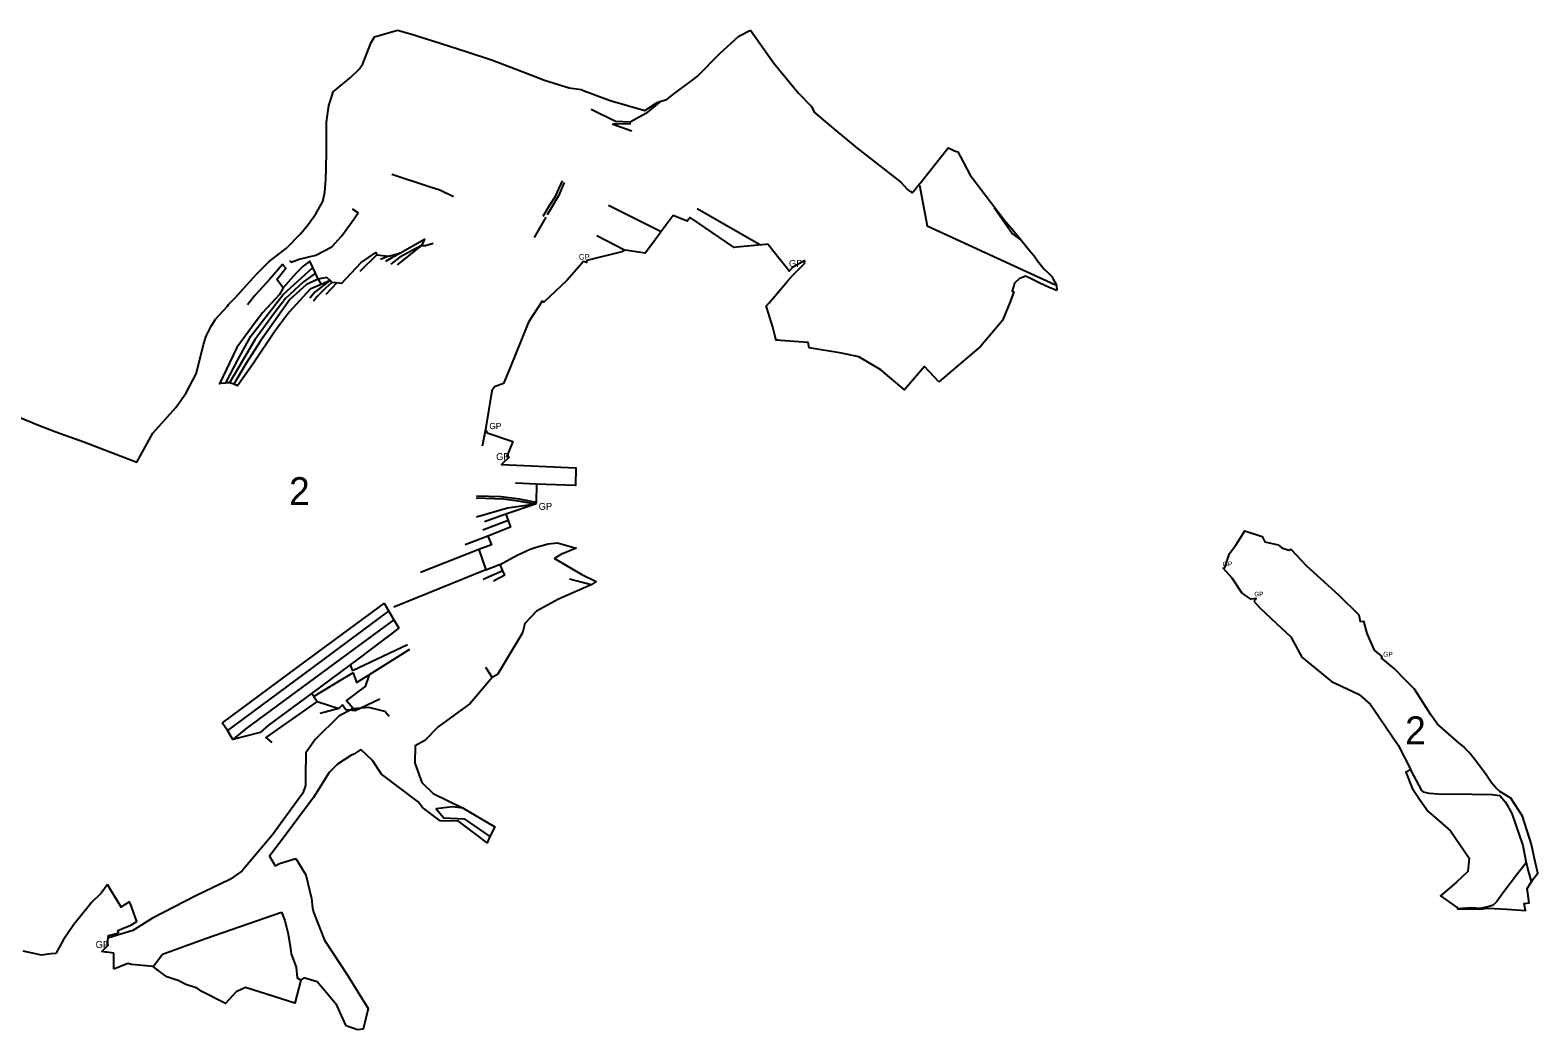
# Model space of a CAD drawing. Extents: x -584576 to -579722, y -1113169 to -1110375.
# Drawn here: x -581887 to -579722, y -1111900 to -1110466 of the extents above; entities that cross this region are included whole.
import ezdxf

# ---------------------------------------------------------------- set-up
doc = ezdxf.new("R2010")
doc.units = 0
for name, color, linetype in [('CESTY', 7, 'Continuous'), ('GRA_ZV', 7, 'Continuous'), ('LES_ZV', 7, 'Continuous'), ('Level 255', 7, 'Continuous'), ('OVNE_PRE', 7, 'Continuous'), ('OVNE_SET', 7, 'Continuous'), ('OVNI_PRE', 7, 'Continuous'), ('OVNI_SET', 7, 'Continuous'), ('VODA', 7, 'Continuous')]:
    doc.layers.add(name, color=color, linetype=linetype)

msp = doc.modelspace()

# ---------------------------------------------------------------- linework, layer by layer
at = {"layer": 'CESTY'}
msp.add_lwpolyline([(-580609.5, -1110688), (-580598.4, -1110746.4), (-580414.4, -1110831.3)], dxfattribs=at)
at = {"layer": 'GRA_ZV'}
for points in [[(-581671.3, -1111831), (-581672.7, -1111830.2), (-581680.3, -1111827.8), (-581690.3, -1111824.6), (-581699.5, -1111817.6), (-581709.9, -1111809.7), (-581696.5, -1111791.9), (-581633.3, -1111769.1), (-581525.9, -1111731.6)], [(-581525.9, -1111731.6), (-581520.9, -1111743.4), (-581516.1, -1111763), (-581512.9, -1111783.8), (-581511.6, -1111791.6), (-581504.7, -1111810.5), (-581503.4, -1111825.7), (-581497.7, -1111829.2), (-581506.3, -1111862.2), (-581577.4, -1111839.9), (-581590.8, -1111845.9), (-581606.2, -1111862.6), (-581640.1, -1111845.6), (-581646.8, -1111840.6), (-581663.1, -1111835.4), (-581666, -1111833.9), (-581671.3, -1111831)]]:
    msp.add_lwpolyline(points, dxfattribs=at)
at = {"layer": 'LES_ZV'}
for p, q in [((-580981.2, -1110567.8), (-581002.5, -1110585.3)), ((-581146.1, -1110734.1), (-581163.1, -1110763.4)), ((-581055.9, -1110716.7), (-580980.7, -1110754.9)), ((-580928.8, -1110721.5), (-580837.9, -1110773.8)), ((-581388.6, -1110788.3), (-581413.1, -1110812.3)), ((-581371.9, -1110790.2), (-581383.6, -1110794.9)), ((-581355.6, -1110785.9), (-581376.1, -1110797.6)), ((-581477.3, -1110841.4), (-581485.1, -1110850.5)), ((-581456.9, -1110825.7), (-581468.8, -1110830.8)), ((-581446.3, -1110828.4), (-581461.8, -1110845)), ((-581474.6, -1110848.2), (-581479.8, -1110854.6)), ((-581232.9, -1111038.7), (-581237.3, -1111062.8)), ((-581159.3, -1111117.2), (-581189.5, -1111115.7)), ((-581161.1, -1111146.2), (-581201.3, -1111151.6)), ((-581201.3, -1111151.6), (-581245.9, -1111164.6)), ((-581203.5, -1111160.5), (-581234.3, -1111171.2)), ((-581200.3, -1111169.5), (-581236.7, -1111183.5)), ((-581242.4, -1111211.2), (-581325.9, -1111244.2)), ((-581229.4, -1111191.9), (-581262.1, -1111204.3)), ((-581232.4, -1111240.4), (-581364.6, -1111293.9)), ((-581208, -1111241.6), (-581236.1, -1111254.2)), ((-581205.1, -1111248.1), (-581221.2, -1111256.7)), ((-581081.1, -1111261.8), (-581112.1, -1111253.9)), ((-581344.9, -1111347.9), (-581423.7, -1111385.2)), ((-581341.8, -1111354.5), (-581400, -1111390.9)), ((-581426.9, -1111376.5), (-581423.7, -1111385.2)), ((-581232.8, -1111380.1), (-581223.1, -1111394.7)), ((-581419.7, -1111442.1), (-581384.7, -1111425.4)), ((-581443.5, -1111439.1), (-581470.3, -1111446.4))]:
    msp.add_line(p, q, dxfattribs=at)
for points in [[(-581002.5, -1110585.3), (-581024.8, -1110597.6), (-581046.3, -1110596.6), (-581080.8, -1110579.4)], [(-581023.9, -1110600.3), (-581050.1, -1110600.6), (-581022.4, -1110610.4)], [(-581278.5, -1110704.7), (-581298.4, -1110695.5), (-581313.4, -1110690.6), (-581367.1, -1110672.7)], [(-581122.8, -1110681.8), (-581127.8, -1110693.2), (-581133.1, -1110705.6), (-581141.3, -1110717.7), (-581150.4, -1110733)], [(-581119.9, -1110684.3), (-581127.9, -1110703.3), (-581144.4, -1110730.9)], [(-581514.3, -1110796.2), (-581511.8, -1110798.6), (-581500.1, -1110794.6), (-581476.2, -1110788.5), (-581453.5, -1110776.9), (-581439.3, -1110761.6), (-581425.1, -1110741.9), (-581415.4, -1110727.8), (-581423.7, -1110722.4)], [(-581439.3, -1110829.1), (-581411.1, -1110799.2), (-581390.4, -1110784.8), (-581388.6, -1110788.3), (-581371.9, -1110790.2), (-581355.6, -1110785.9), (-581320.1, -1110765.6), (-581324.5, -1110774.6), (-581318.8, -1110774.8), (-581307.7, -1110771.6)], [(-581324.5, -1110774.6), (-581355.7, -1110791.6), (-581368.7, -1110801.5)], [(-581324.5, -1110774.6), (-581354.9, -1110798.5), (-581359.6, -1110802.5)], [(-581032, -1110781.3), (-581034.1, -1110781), (-581072.9, -1110760.8)], [(-581439.3, -1110829.1), (-581446.3, -1110828.4), (-581453.2, -1110827.8), (-581455.7, -1110825.2), (-581460.7, -1110820.6), (-581472.9, -1110822.9), (-581476.8, -1110814.7), (-581480.9, -1110806.2), (-581485.2, -1110797.1), (-581494.6, -1110804.4), (-581504.6, -1110814.6), (-581523.4, -1110835.5)], [(-581523.4, -1110835.5), (-581528.5, -1110844.9), (-581552.8, -1110871.6), (-581563.6, -1110885.2), (-581590, -1110921.2), (-581614.7, -1110973.2), (-581613.1, -1110972.3), (-581605.7, -1110972.1), (-581588.3, -1110939), (-581569.5, -1110905), (-581523.4, -1110845), (-581480.9, -1110806.2)], [(-581476.8, -1110814.7), (-581494.1, -1110827.1), (-581519.8, -1110850.6), (-581537, -1110873.1), (-581563.8, -1110910.3), (-581581.9, -1110940.2), (-581600.2, -1110971.9), (-581605.7, -1110972.1)], [(-581472.9, -1110822.9), (-581489.6, -1110830.9), (-581513.5, -1110852.1), (-581556.3, -1110912.7), (-581577, -1110944.4), (-581594.2, -1110973.9), (-581600.2, -1110971.9)], [(-581472.9, -1110822.9), (-581468.8, -1110830.8), (-581484.4, -1110837.5), (-581514.9, -1110870.5), (-581534.8, -1110897.2), (-581566.6, -1110945.3), (-581588.7, -1110976.3), (-581594.2, -1110973.9)], [(-581521.7, -1110804.7), (-581524.4, -1110801.9), (-581543, -1110823.8), (-581563.6, -1110846.1), (-581574.4, -1110860.1)], [(-581523.4, -1110835.5), (-581532.2, -1110823.6), (-581519.3, -1110807.1), (-581521.7, -1110804.7)], [(-581455.7, -1110825.2), (-581456.9, -1110825.7), (-581477.3, -1110841.4)], [(-581453.2, -1110827.8), (-581462.8, -1110836.4), (-581474.6, -1110848.2)], [(-581161.1, -1111146.2), (-581185.7, -1111141.5), (-581206.8, -1111139), (-581246, -1111137.2)], [(-581160, -1111143), (-581162.2, -1111143), (-581184, -1111139), (-581210.5, -1111135.7), (-581245.7, -1111134.6)], [(-581205.1, -1111248.1), (-581208, -1111241.6), (-581211.8, -1111232.4)], [(-581378.1, -1111287.9), (-581490.9, -1111370.9), (-581610.8, -1111460)], [(-581371.6, -1111299.3), (-581468.6, -1111371.2), (-581603.3, -1111471)], [(-581378.1, -1111287.9), (-581364.4, -1111311.9), (-581357.1, -1111324.2)], [(-581364.4, -1111311.9), (-581423.7, -1111355.5), (-581576.6, -1111467.9), (-581595.4, -1111483.8)], [(-581357.1, -1111324.2), (-581415.9, -1111368.3), (-581426.9, -1111376.5), (-581482.5, -1111417.7), (-581544.4, -1111463.1), (-581556.1, -1111473.7)], [(-581422.9, -1111387.9), (-581439, -1111397.8), (-581479.3, -1111421.9), (-581482.5, -1111417.7)], [(-581400, -1111390.9), (-581405.5, -1111407.5), (-581414.2, -1111414), (-581432.2, -1111427.9), (-581419.7, -1111442.1)], [(-581422.9, -1111387.9), (-581417.9, -1111402.2), (-581400, -1111390.9)], [(-581474.6, -1111429.1), (-581548, -1111480.7), (-581539.5, -1111487.9)], [(-581479.3, -1111421.9), (-581474.6, -1111429.1), (-581443.5, -1111439.1), (-581438, -1111434), (-581433.4, -1111440.6), (-581419.7, -1111442.1)], [(-581556.1, -1111473.7), (-581595.4, -1111483.8), (-581603.3, -1111471), (-581610.8, -1111460)], [(-581265, -1111582.5), (-581280.2, -1111580.2), (-581303.5, -1111583.3), (-581292.7, -1111596.4), (-581263.5, -1111597.7), (-581226.4, -1111623)]]:
    msp.add_lwpolyline(points, dxfattribs=at)
at = {"layer": 'Level 255'}
for p, q in [((-581127.9, -1110703.3), (-581127.9, -1110703.3)), ((-581224.3, -1111204.3), (-581224.3, -1111204.3)), ((-581414.5, -1111406.5), (-581414.5, -1111406.5))]:
    msp.add_line(p, q, dxfattribs=at)
at = {"layer": 'OVNE_PRE'}
for p, q in [((-581308.6, -1110481), (-581260.6, -1110496.5)), ((-580928.7, -1110532.1), (-580896.3, -1110499.3)), ((-580076.3, -1111336.6), (-580060.6, -1111365.6)), ((-579978.2, -1111419), (-579962.2, -1111433.2)), ((-581746.4, -1111805.5), (-581746.4, -1111805.5))]:
    msp.add_line(p, q, dxfattribs=at)
for points in [[(-581926, -1111011.8), (-581883.7, -1111028.7), (-581879.2, -1111030.5), (-581849.5, -1111042.4), (-581809.7, -1111056.4), (-581733.6, -1111085.8), (-581710.2, -1111044.1), (-581677.3, -1111007.2), (-581672.4, -1111000.4), (-581662.4, -1110986.4), (-581648.1, -1110959), (-581647.3, -1110955.7), (-581637.7, -1110916.8), (-581634.3, -1110906.4), (-581633.4, -1110903.7), (-581626.5, -1110890.7), (-581621.7, -1110882.7), (-581620.3, -1110880.4), (-581603.3, -1110861.6), (-581601.6, -1110859.6), (-581593.4, -1110851.4), (-581591.5, -1110849.4), (-581575.6, -1110831.4), (-581561.3, -1110815.3), (-581543.5, -1110797.5), (-581518.6, -1110778.4), (-581498.2, -1110758.2), (-581487.6, -1110744.5), (-581476.6, -1110729.4), (-581466.5, -1110711.4), (-581463.6, -1110698.3), (-581462, -1110680.1), (-581461.3, -1110664.1), (-581461, -1110639.9), (-581461, -1110597.8), (-581457.5, -1110573.8), (-581455, -1110565.2), (-581451.7, -1110554.2), (-581427.3, -1110533.9), (-581414.1, -1110521.7), (-581408.7, -1110513.8), (-581397.2, -1110484.4), (-581392, -1110475.4), (-581358.9, -1110465.7)], [(-580896.3, -1110499.3), (-580868.9, -1110474.5), (-580852.1, -1110465.9)], [(-581260.6, -1110496.5), (-581222.9, -1110508.6), (-581173.7, -1110527.6), (-581148, -1110537.5), (-581112.5, -1110548.7), (-581095.3, -1110551), (-581091.1, -1110552.6), (-581078, -1110557.7), (-581053.8, -1110566.5), (-581003.8, -1110580.8), (-580998.6, -1110577.5), (-580986.2, -1110569.4), (-580981.2, -1110567.8), (-580972.4, -1110565.1), (-580964.5, -1110558.9), (-580958.8, -1110554.7), (-580955.1, -1110551.9)]]:
    msp.add_lwpolyline(points, dxfattribs=at)
at = {"layer": 'OVNE_SET'}
for p, q in [((-580980.7, -1110754.9), (-580980.7, -1110754.9)), ((-580521.9, -1110919.5), (-580569.3, -1110959.8)), ((-581212.5, -1111232.7), (-581211.8, -1111232.4)), ((-580125.6, -1111281.4), (-580129.7, -1111285.3)), ((-581334.2, -1111517.8), (-581324, -1111545.7)), ((-581505.1, -1111654.5), (-581490.5, -1111677.8)), ((-581482.1, -1111714.2), (-581482.1, -1111714.2)), ((-581481.2, -1111725.5), (-581481.2, -1111725.5)), ((-581481.2, -1111725.5), (-581479.7, -1111731.5)), ((-581746.4, -1111805.5), (-581766.5, -1111813.6))]:
    msp.add_line(p, q, dxfattribs=at)
for points in [[(-581358.9, -1110465.7), (-581337.3, -1110472.1), (-581328.7, -1110474.6), (-581317.6, -1110478.1), (-581308.6, -1110481)], [(-580852.1, -1110465.9), (-580818.7, -1110513.2), (-580783.3, -1110555.9), (-580765, -1110575), (-580760.4, -1110583.8), (-580732.7, -1110607.4), (-580699.2, -1110634.9), (-580636.2, -1110683.9), (-580627.3, -1110693.7), (-580624, -1110697), (-580621.7, -1110697.5)], [(-580955.1, -1110551.9), (-580937, -1110538.4), (-580928.7, -1110532.1)], [(-580621.7, -1110697.5), (-580620.2, -1110699.3), (-580618.4, -1110697.2), (-580612.3, -1110689.8), (-580608.9, -1110685.8), (-580608.1, -1110684.8), (-580604.7, -1110680.4), (-580568.3, -1110634.8), (-580564.2, -1110636.5), (-580559.2, -1110638.7), (-580554.4, -1110640.5), (-580551, -1110646.7), (-580536.6, -1110673.9), (-580533.4, -1110678.1), (-580487.8, -1110737.9), (-580468.6, -1110760.5), (-580451.6, -1110782.1), (-580444.8, -1110789.6), (-580440, -1110796.7), (-580430.7, -1110808.6), (-580424.9, -1110813.9), (-580419.5, -1110819.3), (-580417.5, -1110823.3), (-580413, -1110831.9), (-580412.4, -1110839.4)], [(-580827.4, -1110772.9), (-580830.9, -1110773.2), (-580872.3, -1110777), (-580875.8, -1110777.4), (-580938.8, -1110734.4), (-580943.1, -1110739.8), (-580963.5, -1110731.5), (-580980.7, -1110754.9), (-580982.6, -1110757.6), (-580995.8, -1110775.8), (-581003.3, -1110785.7), (-581032, -1110781.3), (-581036.9, -1110783.8), (-581087.3, -1110796.1), (-581087.7, -1110799.4), (-581092, -1110797.6), (-581116, -1110825.2), (-581149.1, -1110856), (-581151.6, -1110854.8), (-581171.1, -1110884.9), (-581197.4, -1110949.7), (-581206.7, -1110972.7)], [(-580774.1, -1110796.5), (-580791.9, -1110806.4), (-580796.5, -1110811.7), (-580801.2, -1110806), (-580803.6, -1110803.1), (-580813.5, -1110790.4), (-580827.4, -1110772.9)], [(-580582, -1110970.3), (-580602.3, -1110948.6), (-580630.9, -1110981.7), (-580665.3, -1110953.2), (-580696.7, -1110934.7), (-580721.5, -1110929.2), (-580768.2, -1110921.5), (-580769.2, -1110913.9), (-580809, -1110911), (-580812.7, -1110910.7), (-580815.4, -1110910.5), (-580817.2, -1110903.4), (-580820.1, -1110892.1), (-580828.8, -1110864), (-580829.5, -1110861.7), (-580825.9, -1110857.5), (-580817.2, -1110847.5), (-580799.2, -1110826.1), (-580792.1, -1110817.8), (-580774.8, -1110800.6), (-580774.1, -1110796.5)], [(-580412.4, -1110839.4), (-580416.1, -1110838.1), (-580421, -1110836.1), (-580423.3, -1110835.1), (-580435.7, -1110829.2), (-580451.2, -1110821.5), (-580457.5, -1110818.8), (-580466.5, -1110822.5), (-580473.2, -1110828.7)], [(-580473.2, -1110828.7), (-580476.6, -1110840.3), (-580474.1, -1110841.5), (-580479.4, -1110855.7), (-580490.5, -1110882.4), (-580521.9, -1110919.5)], [(-581206.7, -1110972.7), (-581219.8, -1110977.8), (-581223.8, -1110983.4), (-581232.9, -1111038.7)], [(-580569.3, -1110959.8), (-580570.3, -1110960.7), (-580573.4, -1110963.3), (-580582, -1110970.3)], [(-581232.9, -1111038.7), (-581230.4, -1111043.6), (-581193.4, -1111055.9), (-581202.1, -1111077.1), (-581198.7, -1111078.7), (-581209.8, -1111089.1), (-581103, -1111093.7), (-581103.6, -1111119.1), (-581159.3, -1111117.2), (-581160, -1111143), (-581161.1, -1111146.2), (-581203.5, -1111160.5), (-581200.3, -1111169.5)], [(-581200.3, -1111169.5), (-581196.9, -1111179.1), (-581229.4, -1111191.9)], [(-580125.6, -1111281.4), (-580133.9, -1111282.6), (-580146.5, -1111273.2), (-580160.7, -1111252), (-580173.5, -1111237.8), (-580171.3, -1111236.8), (-580164.4, -1111216.8), (-580155.1, -1111205), (-580142.3, -1111184.4), (-580117.5, -1111192.4), (-580113.7, -1111199.9), (-580094.4, -1111204.5), (-580089.1, -1111208.9), (-580079.3, -1111212.2), (-580076.5, -1111210.8), (-580053.8, -1111234.5), (-580008, -1111276.3), (-579978.5, -1111304.8), (-579976.7, -1111314.4), (-579971.8, -1111314), (-579967.2, -1111331.5), (-579956.7, -1111355.7), (-579945.7, -1111364.6), (-579946.4, -1111366.8)], [(-581211.8, -1111232.4), (-581187.4, -1111219.2), (-581168.5, -1111210.4), (-581159.8, -1111207.5), (-581142.6, -1111203.1), (-581129.2, -1111201.6), (-581102.5, -1111209.1), (-581124.7, -1111218.2), (-581133.7, -1111224.1), (-581094.6, -1111246.9), (-581073.9, -1111256.9), (-581081.1, -1111261.8), (-581128, -1111282.4), (-581159.3, -1111299.8), (-581176.2, -1111317.1), (-581179.8, -1111330.6), (-581215.4, -1111390.3), (-581223.1, -1111394.7), (-581254.9, -1111432), (-581300.5, -1111465.7), (-581320, -1111485), (-581333.5, -1111492.7), (-581334.2, -1111517.8)], [(-581229.4, -1111191.9), (-581224.3, -1111204.3), (-581242.4, -1111211.2), (-581232.4, -1111240.4), (-581212.5, -1111232.7)], [(-580129.7, -1111285.3), (-580120.2, -1111295.4), (-580089.9, -1111323.9), (-580076.3, -1111336.6)], [(-580060.6, -1111365.6), (-580047, -1111376.7), (-580018.1, -1111400.3), (-579988.4, -1111414.2), (-579978.2, -1111419)], [(-579962.2, -1111433.2), (-579957.8, -1111439.8), (-579922.4, -1111491.9), (-579921.6, -1111493), (-579904.7, -1111526.5), (-579910.5, -1111530.4), (-579911, -1111530.7), (-579902, -1111553.4), (-579890.4, -1111570.7), (-579879, -1111587.1), (-579862.3, -1111601.4), (-579846.9, -1111615.1), (-579820.1, -1111654.2), (-579822, -1111673.2), (-579839, -1111689.2), (-579861.6, -1111708.1), (-579837.1, -1111725.5), (-579836.9, -1111727), (-579801.2, -1111726.6), (-579797.1, -1111726.3), (-579793.6, -1111726), (-579766, -1111727.5), (-579739.6, -1111729.3), (-579740, -1111727), (-579741.3, -1111719.2), (-579734.3, -1111718.1), (-579737, -1111697.8), (-579732.7, -1111690.8), (-579728.9, -1111684.9), (-579721.7, -1111675.7), (-579727, -1111652.9), (-579730.7, -1111634.6), (-579743.8, -1111593.9), (-579760.6, -1111568.2), (-579776.3, -1111558.5), (-579781.4, -1111553.6), (-579788.2, -1111546.2), (-579796, -1111534.5), (-579802, -1111525.8), (-579812.5, -1111512), (-579818.6, -1111504.9), (-579820.8, -1111501.8), (-579826.5, -1111496.4), (-579828, -1111494.2), (-579834.4, -1111488.9), (-579865.8, -1111461.6), (-579875.1, -1111448.2), (-579898.8, -1111411.7), (-579910.8, -1111399.5), (-579927.8, -1111381.9), (-579944.9, -1111368), (-579946.4, -1111366.8)], [(-581411.6, -1111498.2), (-581421.9, -1111504.8), (-581426.1, -1111506.9), (-581445.4, -1111519.3), (-581457.1, -1111531.1), (-581479.7, -1111566.8), (-581523.3, -1111625.5)], [(-581324, -1111545.7), (-581307.8, -1111561.3), (-581265, -1111582.5), (-581219.3, -1111609), (-581226.4, -1111623), (-581230.2, -1111632.1), (-581271.6, -1111600.9), (-581297.8, -1111600.7), (-581323.2, -1111581.6), (-581329.6, -1111573.3), (-581382, -1111533.3), (-581395.1, -1111514.1), (-581411.6, -1111498.2)], [(-581523.3, -1111625.5), (-581543, -1111651.2), (-581535, -1111664.9), (-581528.6, -1111661.6), (-581505.1, -1111654.5)], [(-581490.5, -1111677.8), (-581482.6, -1111712.2), (-581481.2, -1111725.5)], [(-581479.7, -1111731.5), (-581463.8, -1111771.7), (-581431, -1111822), (-581401.2, -1111870.1), (-581408.5, -1111899.3), (-581416.5, -1111900.5), (-581432.8, -1111894.6), (-581446.3, -1111865.1), (-581461.2, -1111847.5), (-581474.5, -1111831.7), (-581493.4, -1111825.8)], [(-581663.1, -1111835.4), (-581666, -1111833.9), (-581671.3, -1111831), (-581672.7, -1111830.2), (-581680.3, -1111827.8), (-581690.3, -1111824.6), (-581699.5, -1111817.6), (-581704.6, -1111813.7), (-581709.9, -1111809.7), (-581740.9, -1111806.8), (-581746.4, -1111805.5)], [(-581497.7, -1111829.2), (-581506.3, -1111862.2), (-581577.4, -1111839.9), (-581590.8, -1111845.9), (-581606.2, -1111862.6), (-581640.1, -1111845.6), (-581646.8, -1111840.6), (-581658.7, -1111836.8), (-581663.1, -1111835.4)], [(-581493.4, -1111825.8), (-581495.5, -1111827.5), (-581497.7, -1111829.2)]]:
    msp.add_lwpolyline(points, dxfattribs=at)
at = {"layer": 'OVNI_PRE'}
for p, q in [((-581857.1, -1111791.6), (-581870.1, -1111793.2)), ((-581766.5, -1111790.6), (-581776.7, -1111789.2))]:
    msp.add_line(p, q, dxfattribs=at)
msp.add_lwpolyline([(-581870.1, -1111793.2), (-581883.1, -1111790.6), (-581896.6, -1111787.7)], dxfattribs=at)
at = {"layer": 'OVNI_SET'}
for p, q in [((-581770.7, -1111699.9), (-581775.5, -1111692)), ((-581754.8, -1111755.3), (-581741.8, -1111750.3)), ((-581849.8, -1111791), (-581857.1, -1111791.6)), ((-581776.7, -1111789.2), (-581778.5, -1111788.9)), ((-581766.5, -1111813.6), (-581766.5, -1111790.6))]:
    msp.add_line(p, q, dxfattribs=at)
for points in [[(-581775.5, -1111692), (-581784.6, -1111704.1), (-581798.7, -1111717.7)], [(-581742.9, -1111719), (-581743.8, -1111716.6), (-581756.2, -1111724.3), (-581756.5, -1111723.6), (-581770.7, -1111699.9)], [(-581798.7, -1111717.7), (-581802, -1111721.8), (-581824.1, -1111749.4)], [(-581741.8, -1111750.3), (-581733.4, -1111745), (-581742.6, -1111719.8), (-581742.9, -1111719)], [(-581824.1, -1111749.4), (-581839.2, -1111772), (-581849.8, -1111791)], [(-581775.6, -1111776.2), (-581774.2, -1111765), (-581759.4, -1111761.1)], [(-581759.4, -1111761.1), (-581760.7, -1111757.9), (-581754.8, -1111755.3)], [(-581778.5, -1111788.9), (-581783.8, -1111787.9), (-581774.4, -1111778.9), (-581775.6, -1111776.2)]]:
    msp.add_lwpolyline(points, dxfattribs=at)
at = {"layer": 'VODA'}
for points in [[(-580502.2, -1110720), (-580475.9, -1110758), (-580464.5, -1110766.5)], [(-581371.1, -1111450.9), (-581377.4, -1111443.5), (-581400.3, -1111438), (-581423.9, -1111439.8), (-581443.5, -1111450.2), (-581477.2, -1111483.8), (-581490.5, -1111503), (-581491.2, -1111537), (-581491.2, -1111549.9), (-581494.9, -1111561), (-581538.5, -1111620.8), (-581582.8, -1111672.9), (-581599.8, -1111684.7), (-581648.6, -1111708), (-581711.1, -1111740.2), (-581739.2, -1111757.9), (-581773.5, -1111768.2)], [(-579904.7, -1111526.5), (-579904.1, -1111528.4), (-579888.7, -1111556.8), (-579886.1, -1111559), (-579877.5, -1111560.6), (-579865, -1111561.9), (-579815.8, -1111562.2), (-579787.9, -1111562.5), (-579776.1, -1111564.3), (-579768.3, -1111573.8), (-579758.9, -1111590.1), (-579743.4, -1111635.8), (-579738.6, -1111661), (-579734.4, -1111675.8), (-579731.4, -1111687.4)], [(-579738.6, -1111661), (-579751.1, -1111676.6), (-579770.6, -1111702.4), (-579780.7, -1111716.2), (-579785.9, -1111721.6), (-579789.9, -1111723.1), (-579804.1, -1111726.3), (-579817.9, -1111725.3), (-579836.9, -1111727)]]:
    msp.add_lwpolyline(points, dxfattribs=at)

# ---------------------------------------------------------------- texts
at = {"layer": 'Level 255'}
for s, height, p in [('GP', 8.1, (-581098.7, -1110795.1)), ('GP', 10, (-580797, -1110805.4)), ('GP', 8.9, (-581227.2, -1111038.3)), ('GP', 10, (-581217.5, -1111082.8)), ('2', 40, (-581514.8, -1111147.3)), ('GP', 10, (-581156.4, -1111154.2)), ('GP', 7, (-580174.4, -1111235.4)), ('GP', 6.5, (-580128.8, -1111278.3)), ('GP', 7, (-579943.8, -1111365)), ('2', 40, (-579912.3, -1111490.6)), ('GP', 10, (-581792.5, -1111783))]:
    msp.add_text(s, height=height, dxfattribs=at).set_placement(p)

doc.saveas('drawing.dxf')
